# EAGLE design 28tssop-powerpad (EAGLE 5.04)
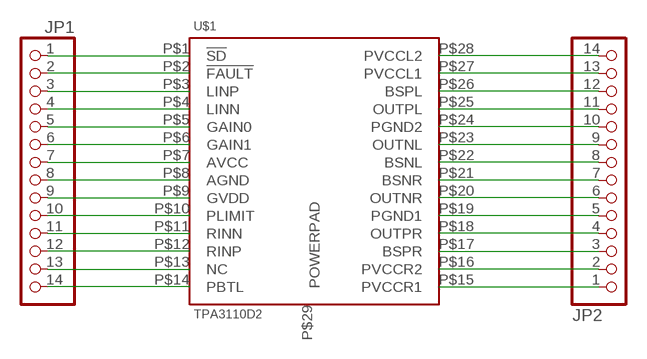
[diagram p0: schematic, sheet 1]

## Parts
JP1  PINHD-1X14  [1X14]
JP2  PINHD-1X14  [1X14]
U$1  TPA3110D2  [TSSOP28]

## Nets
N$1: JP1.1 U$1.P$1(!SD)
N$2: JP1.2 U$1.P$2(!FAULT)
N$3: JP1.3 U$1.P$3(LINP)
N$4: JP1.4 U$1.P$4(LINN)
N$5: JP1.5 U$1.P$5(GAIN0)
N$6: JP1.6 U$1.P$6(GAIN1)
N$7: JP1.7 U$1.P$7(AVCC)
N$8: JP1.8 U$1.P$8(AGND)
N$9: JP1.9 U$1.P$9(GVDD)
N$10: JP1.10 U$1.P$10(PLIMIT)
N$11: JP1.11 U$1.P$11(RINN)
N$12: JP1.12 U$1.P$12(RINP)
N$13: JP1.13 U$1.P$13(NC)
N$14: JP1.14 U$1.P$14(PBTL)
N$15: JP2.1 U$1.P$15(PVCCR1)
N$16: JP2.2 U$1.P$16(PVCCR2)
N$17: JP2.3 U$1.P$17(BSPR)
N$18: JP2.4 U$1.P$18(OUTPR)
N$19: JP2.5 U$1.P$19(PGND1)
N$20: JP2.6 U$1.P$20(OUTNR)
N$21: JP2.7 U$1.P$21(BSNR)
N$22: JP2.8 U$1.P$22(BSNL)
N$23: JP2.9 U$1.P$23(OUTNL)
N$24: JP2.10 U$1.P$24(PGND2)
N$25: JP2.11 U$1.P$25(OUTPL)
N$26: JP2.12 U$1.P$26(BSPL)
N$27: JP2.13 U$1.P$27(PVCCL1)
N$28: JP2.14 U$1.P$28(PVCCL2)
Unconnected: U$1.P$29(POWERPAD)

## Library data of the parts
JP1 JP2 = pinhead:PINHD-1X14: PIN HEADER
U$1 = trl:TPA3110D2

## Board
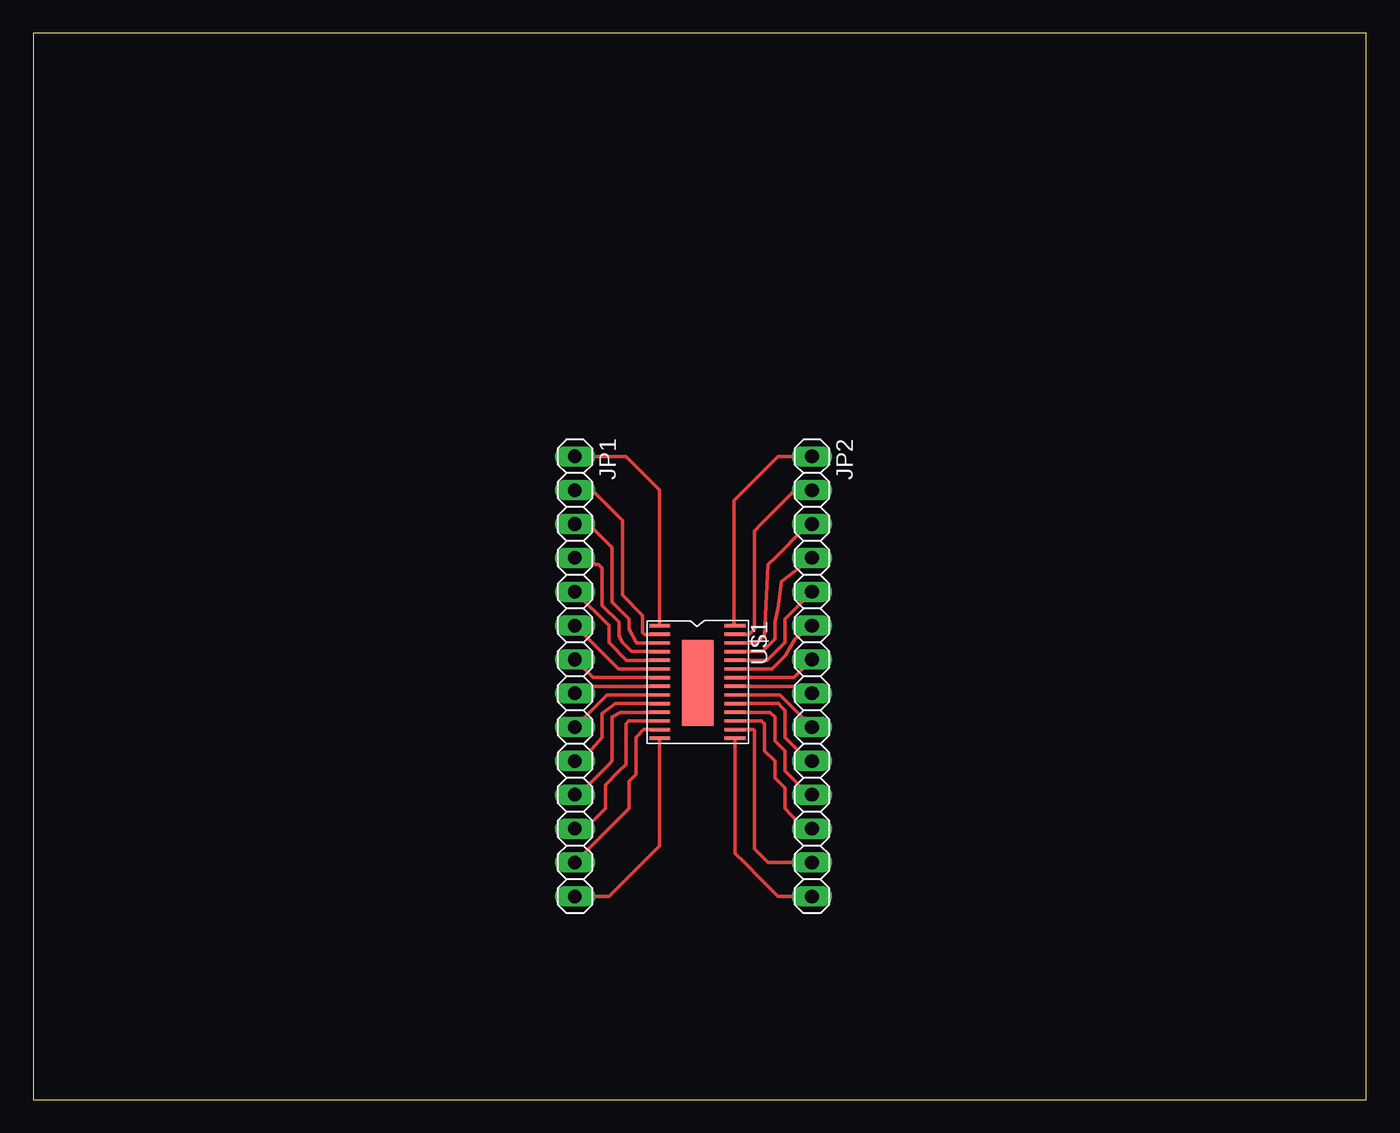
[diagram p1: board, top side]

Size 100 x 80 mm. Coordinates in mm from the lower left corner, seen from the top.
Outline: 0,0 100,0 100,80 0,80 0,0
Copper layers (1*16): Top 0.035mm / dielectric 1.5mm / Bottom 0.035mm
Design rules "default": minimum track width 10mil, minimum drill 24mil, track to track 8mil, track to pad 8mil, pad to pad 8mil, via to via 8mil, smd to smd 8mil, copper to edge 40mil, drill to drill 8mil, minimum pad ring 10mil, minimum via ring 8mil, stop-mask expansion 4mil, vias tented up to drill 0mil, thermal gap 10mil

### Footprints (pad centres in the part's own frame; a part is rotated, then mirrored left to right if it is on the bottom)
1X14 = drill 1.016 long: 1 -16.51,0; 2 -13.97,0; 3 -11.43,0; 4 -8.89,0; 5 -6.35,0; 6 -3.81,0; 7 -1.27,0; 8 1.27,0; 9 3.81,0; 10 6.35,0; 11 8.89,0; 12 11.43,0; 13 13.97,0; 14 16.51,0
TSSOP28 = smd 0.25 x 1.55: P$1 0,0; P$2 0.65,0; P$3 1.3,0; P$4 1.95,0; P$5 2.6,0; P$6 3.25,0; P$7 3.9,0; P$8 4.55,0; P$9 5.2,0; P$10 5.85,0; P$11 6.5,0; P$12 7.15,0; P$13 7.8,0; P$14 8.45,0; P$15 0,5.65; P$16 0.65,5.65; P$17 1.3,5.65; P$18 1.95,5.65; P$19 2.6,5.65; P$20 3.25,5.65; P$21 3.9,5.65; P$22 4.55,5.65; P$23 5.2,5.65; P$24 5.85,5.65; P$25 6.5,5.65; P$26 7.15,5.65; P$27 7.8,5.65; P$28 8.45,5.65 | smd 6.46 x 2.35: P$29 4.3,2.85

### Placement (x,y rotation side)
JP1  40.64,31.75 270 top
JP2  58.42,31.75 270 top
U$1  46.99,35.56 270 top

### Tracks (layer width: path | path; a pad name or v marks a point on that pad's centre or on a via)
N$1
  Top 0.254: U$1.P$1 46.99,45.72 44.45,48.26 JP1.1
N$2
  Top 0.254: U$1.P$2 45.86,34.91 45.72,35.05 45.72,36.32 44.2,37.85 44.2,43.43 43.94,43.69 41.91,45.72 JP1.2
N$3
  Top 0.254: U$1.P$3 45.24,34.26 44.7,35.31 44.7,36.07 43.43,37.34 43.43,41.4 43.18,41.66 41.4,43.43 40.89,43.43 JP1.3
N$4
  Top 0.254: U$1.P$4 44.88,33.61 44.2,34.29 43.94,34.8 43.94,35.81 42.67,37.08 42.67,39.88 42.42,40.13 42.16,40.13 41.4,40.89 40.89,40.89 JP1.4
N$5
  Top 0.254: U$1.P$5 44.51,32.96 43.18,34.29 43.18,35.56 JP1.5
N$6
  Top 0.254: U$1.P$6 43.89,32.31 43.18,33.02 JP1.6
N$7
  Top 0.254: U$1.P$7 42,31.66 41.91,31.75 JP1.7
N$8
  Top 0.254: U$1.P$8 41.17,31.01 JP1.8
N$9
  Top 0.254: U$1.P$9 43.06,30.36 JP1.9
N$10
  Top 0.254: U$1.P$10 43.68,29.71 42.67,28.96 42.67,27.18 41.15,25.4 JP1.10
N$11
  Top 0.254: U$1.P$11 44.05,29.06 43.43,28.7 43.43,27.18 43.43,26.92 43.43,25.4 43.18,25.15 41.66,23.62 41.15,23.11 40.89,23.11 JP1.11
N$12
  Top 0.254: U$1.P$12 44.67,28.41 44.45,28.19 44.45,25.15 43.94,24.64 42.93,23.62 42.93,21.84 41.4,20.32 JP1.12
N$13
  Top 0.254: JP1.13 44.7,21.84 44.7,23.88 45.21,24.38 45.21,27.18 45.79,27.76 U$1.P$13
N$14
  Top 0.254: U$1.P$14 46.99,19.05 43.18,15.24 JP1.14
N$15
  Top 0.254: JP2.1 55.88,48.26 52.58,44.96 52.58,35.62 U$1.P$15
N$16
  Top 0.254: U$1.P$16 53.71,34.91 54.1,35.31 54.1,42.67 54.61,43.18 57.15,45.72 JP2.2
N$17
  Top 0.254: U$1.P$17 54.33,34.26 54.36,34.29 54.61,34.54 54.86,34.8 55.12,40.13 55.63,40.64 57.91,42.93 58.17,42.93 JP2.3
N$18
  Top 0.254: U$1.P$18 54.69,33.61 55.63,34.54 55.63,35.81 55.88,36.83 56.13,38.86 JP2.4
N$19
  Top 0.254: U$1.P$19 55.06,32.96 56.39,34.29 56.39,36.07 JP2.5
N$20
  Top 0.254: U$1.P$20 55.42,32.31 56.44,33.33 57.15,34.54 JP2.6
N$21
  Top 0.254: U$1.P$21 57.06,31.66 JP2.7
N$22
  Top 0.254: U$1.P$22 57.89,31.01 JP2.8
N$23
  Top 0.254: U$1.P$23 56,30.36 56.39,29.97 JP2.9
N$24
  Top 0.254: U$1.P$24 55.89,29.71 56.13,29.46 56.39,29.21 56.39,27.18 56.64,26.92 57.91,25.65 58.17,25.65 JP2.10
N$25
  Top 0.254: U$1.P$25 55.27,29.06 55.63,28.7 55.63,27.18 55.63,26.92 56.39,26.16 56.39,24.64 56.64,24.38 57.91,23.11 58.17,23.11 JP2.11
N$26
  Top 0.254: U$1.P$26 54.65,28.41 54.86,28.19 54.86,26.16 55.63,25.4 55.63,24.13 56.39,23.37 56.39,21.84 56.9,21.34 57.66,20.57 58.17,20.57 JP2.12
N$27
  Top 0.254: U$1.P$27 54.03,27.76 54.1,27.69 54.1,18.8 55.12,17.78 JP2.13
N$28
  Top 0.254: U$1.P$28 52.64,18.48 53.34,17.78 54.61,16.51 55.88,15.24 JP2.14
